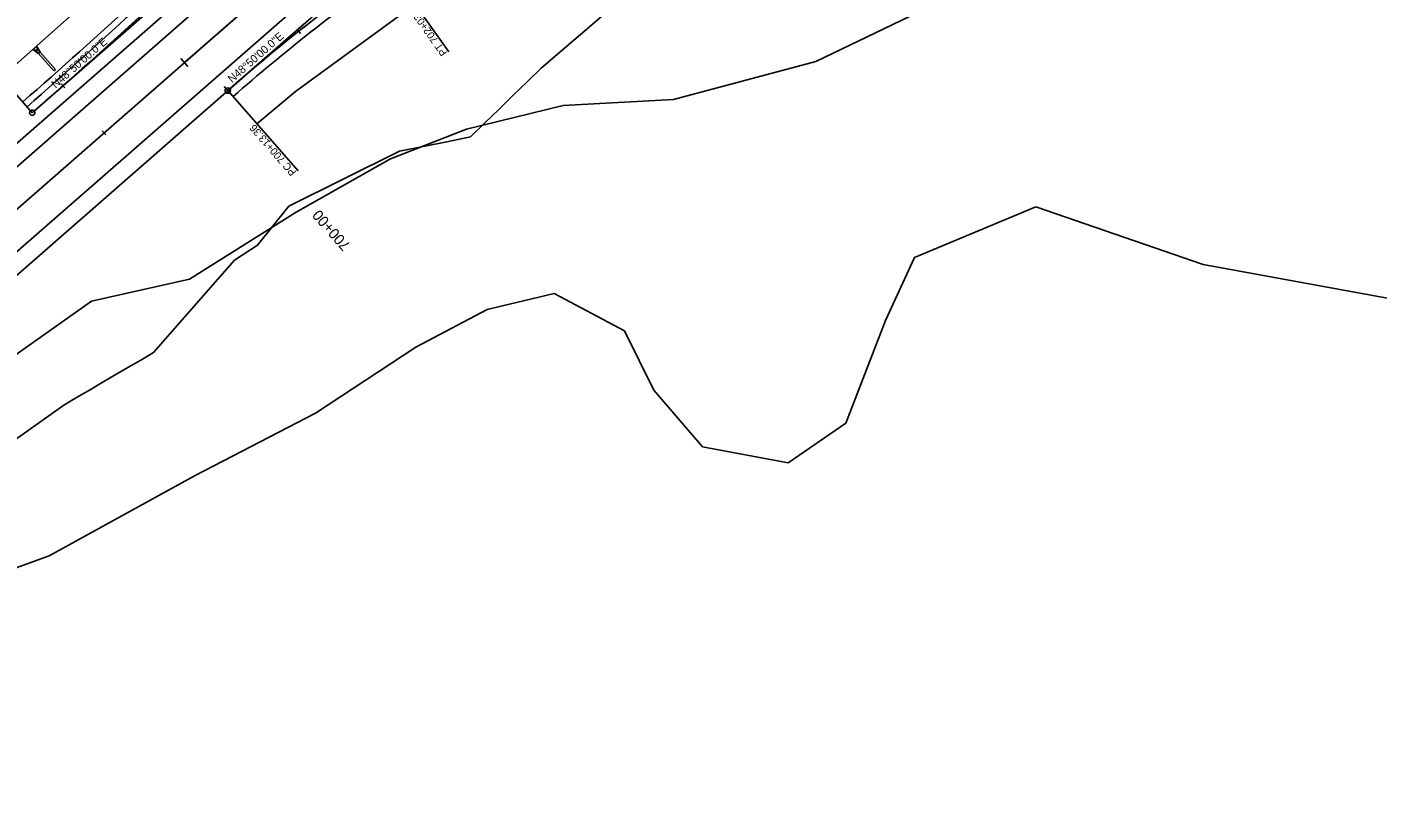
# Model space of a CAD drawing. Extents: x 1300404 to 1323571, y 234004 to 252077.
# Drawn here: x 1309033 to 1310298, y 238902 to 239629 of the extents above; entities that cross this region are included whole.
import ezdxf

# ---------------------------------------------------------------- set-up
doc = ezdxf.new("R2010")
doc.units = 0
for name, color, linetype in [('R_Const Limits', 7, 'Continuous'), ('R_Draft', 7, 'Continuous'), ('R_Flooplain', 7, 'Continuous'), ('R_Horz Alg Annot', 7, 'Continuous'), ('R_Horz Alg Annot Leader', 7, 'Continuous'), ('R_Horz Alg Major Ticks', 7, 'Continuous'), ('R_Horz Alg Minor Ticks', 7, 'Continuous'), ('R_Horz Alg Station Annot', 7, 'Continuous'), ('R_Horz Alg Tangents', 7, 'Continuous'), ('R_Horz Alg Tangents Text', 7, 'Continuous'), ('R_Lane Edge', 7, 'Continuous'), ('R_Pipe Culvert', 7, 'Continuous'), ('R_Proposed', 7, 'Continuous'), ('R_Shoulder', 7, 'Continuous')]:
    doc.layers.add(name, color=color, linetype=linetype)

msp = doc.modelspace()

# ---------------------------------------------------------------- linework, layer by layer
at = {"layer": 'R_Const Limits'}
for points in [[(1309611.5, 239807.3), (1309284.5, 239568.2), (1309248.3, 239537.7)], [(1309161.2, 239746.2), (1309174.8, 239731.1), (1309163.8, 239720.3), (1309126.4, 239686.2), (1309041.9, 239610.6), (1308690.7, 239296.8), (1308488.4, 239084.8)], [(1308978.5, 239211.1), (1309067.3, 239274.1), (1309079.3, 239281.2), (1309091.3, 239288.2), (1309103.4, 239295.2), (1309115.4, 239302.3), (1309127.4, 239309.3), (1309139.4, 239316.3), (1309151.5, 239323.4), (1309227.2, 239409.9), (1309248.9, 239424), (1309278.4, 239460.5), (1309382.1, 239512.2), (1309404.2, 239516.6), (1309426.4, 239521), (1309448.5, 239525.5), (1309461.8, 239538.4), (1309475.1, 239551.3), (1309488.3, 239564.2), (1309501.6, 239577.1), (1309514.9, 239590), (1309588.6, 239653)]]:
    msp.add_lwpolyline(points, dxfattribs=at)
at = {"layer": 'R_Draft'}
for p, q in [((1308397, 238971.9), (1312368.4, 242444.5)), ((1308407.8, 238959.5), (1312379.2, 242432.1)), ((1308447.3, 238914.3), (1312418.7, 242386.9)), ((1308458.2, 238901.9), (1312429.6, 242374.5)), ((1309037.8, 239548.2), (1312137.6, 242258.7))]:
    msp.add_line(p, q, dxfattribs=at)
at = {"layer": 'R_Flooplain'}
for p, q in [((1309892.5, 239654.2), (1309772.3, 239596.1)), ((1309772.3, 239596.1), (1309638.7, 239560.5)), ((1309638.7, 239560.5), (1309535.5, 239554.8)), ((1309535.5, 239554.8), (1309444.9, 239532.8)), ((1309444.9, 239532.8), (1309373.4, 239504.9)), ((1309373.4, 239504.9), (1309285, 239454.9)), ((1309864.8, 239412.4), (1309978.4, 239459.9)), ((1309978.4, 239459.9), (1310135.4, 239406)), ((1309285, 239454.9), (1309185.1, 239392.2)), ((1309837.6, 239353.3), (1309864.8, 239412.4)), ((1310135.4, 239406), (1310345.2, 239367.6)), ((1309185.1, 239392.2), (1309093.3, 239371.4)), ((1308757.3, 239134.3), (1309093.3, 239371.4)), ((1309464.3, 239363.6), (1309526.8, 239378.6)), ((1309526.8, 239378.6), (1309592.8, 239343.8)), ((1309397.2, 239328.3), (1309464.3, 239363.6)), ((1309592.8, 239343.8), (1309620.3, 239288)), ((1309800.2, 239257.2), (1309837.6, 239353.3)), ((1309303.4, 239266.5), (1309397.2, 239328.3)), ((1309620.3, 239288), (1309666, 239234.9)), ((1309190.4, 239208.1), (1309303.4, 239266.5)), ((1309746.3, 239220), (1309800.2, 239257.2)), ((1309666, 239234.9), (1309746.3, 239220)), ((1309053.6, 239132.7), (1309190.4, 239208.1)), ((1308935.3, 239090.2), (1309053.6, 239132.7))]:
    msp.add_line(p, q, dxfattribs=at)
at = {"layer": 'R_Horz Alg Annot Leader'}
for points in [[(1309370.3, 239686.9), (1309428.3, 239605.4)], [(1309037.8, 239548.2), (1308972, 239623.5)], [(1309221, 239568.9), (1309286.9, 239493.7)]]:
    msp.add_lwpolyline(points, dxfattribs=at)
at = {"layer": 'R_Horz Alg Major Ticks'}
for points in [[(1309177.1, 239598.9), (1309183.7, 239591.4)], [(1309217.7, 239572.7), (1309224.3, 239565.2)], [(1309217.7, 239572.7), (1309224.3, 239565.2)]]:
    msp.add_lwpolyline(points, dxfattribs=at)
at = {"layer": 'R_Horz Alg Minor Ticks'}
for points in [[(1309286, 239626.4), (1309289.1, 239622.5)], [(1309064.8, 239575.3), (1309068.2, 239571.6)], [(1309103.4, 239531.2), (1309106.7, 239527.5)]]:
    msp.add_lwpolyline(points, dxfattribs=at)
at = {"layer": 'R_Horz Alg Tangents'}
for p, q in [((1309037.8, 239548.2), (1309145.3, 239642.2)), ((1309221, 239568.9), (1309292.7, 239631.6))]:
    msp.add_line(p, q, dxfattribs=at)
at = {"layer": 'R_Lane Edge'}
for centre, radius, start, end in [((1305266.3, 243861.4), 5722.1, 311.1667, 314.0235), ((1310478.2, 238131.2), 1902.4, 125.4583, 131.1667)]:
    msp.add_arc(centre, radius, start, end, dxfattribs=at)
at = {"layer": 'R_Pipe Culvert'}
for p, q in [((1309038.5, 239607.6), (1309041.9, 239610.6)), ((1309043.3, 239603.7), (1309038.5, 239607.6)), ((1309041.7, 239606.2), (1309038.5, 239607.6)), ((1309043.3, 239604), (1309038.7, 239607.8)), ((1309038.7, 239607.8), (1309041.7, 239606.2)), ((1309044.9, 239605.3), (1309041.7, 239610.4)), ((1309042.8, 239607.3), (1309041.7, 239610.4)), ((1309045.2, 239605.3), (1309041.9, 239610.6)), ((1309041.9, 239610.6), (1309042.8, 239607.3)), ((1309043.3, 239603.7), (1309045.2, 239605.3)), ((1309043.3, 239604), (1309044.9, 239605.3)), ((1309057.9, 239587.5), (1309043.3, 239604)), ((1309043.3, 239604), (1309043.3, 239603.7)), ((1309059.4, 239588.8), (1309044.8, 239605.3)), ((1309044.9, 239605.3), (1309045.2, 239605.3)), ((1309057.9, 239587.5), (1309059.4, 239588.8))]:
    msp.add_line(p, q, dxfattribs=at)
msp.add_arc((1309042, 239607), 0.857, 246.4802, 20.011, dxfattribs=at)
at = {"layer": 'R_Proposed'}
for p, q in [((1308463.1, 238968), (1312793.8, 242754.8)), ((1308427.6, 238936.9), (1312399, 242409.5)), ((1309180.4, 239595.2), (1312399, 242409.5)), ((1309180.4, 239595.2), (1312399, 242409.5)), ((1309180.4, 239595.2), (1312051.5, 242105.7))]:
    msp.add_line(p, q, dxfattribs=at)
for centre in [(1309221, 239568.9), (1309037.8, 239548.2)]:
    msp.add_circle(centre, 2.5, dxfattribs=at)
for centre, radius, start, end in [((1305266.3, 243861.4), 5729.6, 311.16667, 314.02346), ((1310478.2, 238131.2), 1909.9, 125.4583, 131.1667), ((1310478.2, 238131.2), 1909.9, 125.4583, 131.1667), ((1310478.2, 238131.2), 1909.9, 125.4583, 131.1667), ((1310478.2, 238131.2), 1909.9, 125.4583, 131.1667), ((1310478.2, 238131.2), 1909.9, 125.4583, 131.1667)]:
    msp.add_arc(centre, radius, start, end, dxfattribs=at)
at = {"layer": 'R_Shoulder'}
msp.add_arc((1305266.3, 243861.4), 5716.1, 311.1667, 314.0235, dxfattribs=at)

# ---------------------------------------------------------------- texts
at = {"layer": 'R_Horz Alg Annot'}
for s, rotation, p in [('PT 702+03.64', 125.4583, (1309427.1, 239604.5)), ('PC 700+13.36', 131.1667, (1309285.7, 239492.7))]:
    msp.add_text(s, height=7, rotation=rotation, dxfattribs=at).set_placement(p)
at = {"layer": 'R_Horz Alg Station Annot'}
msp.add_text('700+00', height=10, rotation=131.1667, dxfattribs=at).set_placement((1309336.6, 239424.2))
at = {"layer": 'R_Horz Alg Tangents Text'}
for p in [(1309225, 239575.8), (1309059.7, 239570.7)]:
    msp.add_text('N48%%d50\'00.0"E', height=7.5, rotation=41.1667, dxfattribs=at).set_placement(p)

doc.saveas('drawing.dxf')
